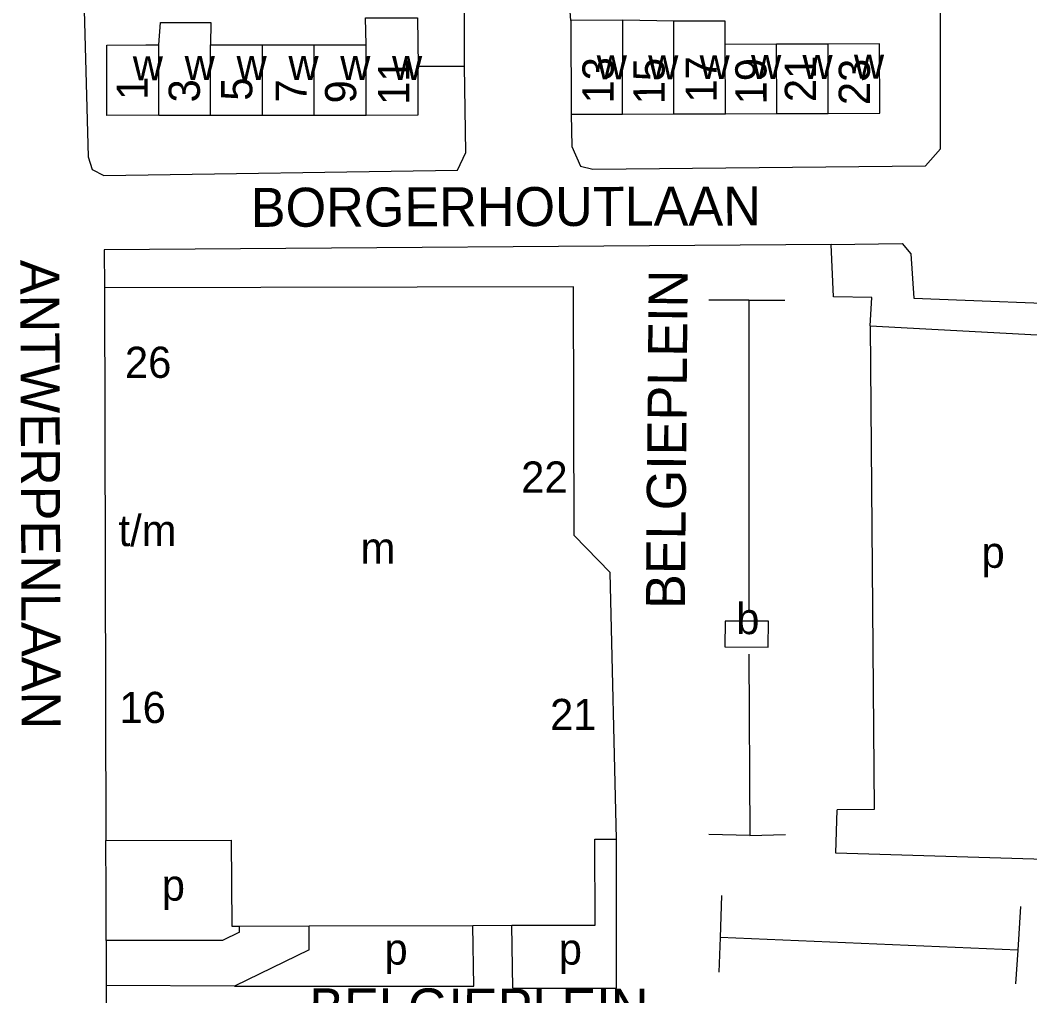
# Model space of a CAD drawing. Extents: x 159675 to 162108, y 386471 to 388472.
# Drawn here: x 161304.5 to 161434, y 387808.6 to 387933.7 of the extents above; entities that cross this region are included whole.
import ezdxf

# ---------------------------------------------------------------- set-up
doc = ezdxf.new("R2010")
doc.units = 0
for name, color, linetype in [('BLT_Basislijn', 7, 'Continuous'), ('BLT_Bebouwing', 7, 'Continuous'), ('BLT_Centroide', 7, 'Continuous'), ('BLT_Huisnummer', 7, 'Continuous'), ('BLT_Huisnummer_ tussenligend', 7, 'Continuous'), ('BLT_Huisnummer_reeks', 7, 'Continuous'), ('BLT_Onderverdeling_panden', 7, 'Continuous'), ('BLT_Straatnaam', 7, 'Continuous')]:
    doc.layers.add(name, color=color, linetype=linetype)

msp = doc.modelspace()

# ---------------------------------------------------------------- linework, layer by layer
at = {"layer": 'BLT_Basislijn'}
for p, q in [((161375.14, 387933.65), (161374.57, 387941.33)), ((161397.94, 387897.77), (161392.79, 387897.77)), ((161397.94, 387897.77), (161397.94, 387857.87)), ((161397.94, 387897.77), (161402.54, 387897.77)), ((161397.94, 387852.39), (161398.05, 387829.15)), ((161398.05, 387829.15), (161392.79, 387829.26)), ((161398.05, 387829.15), (161402.65, 387829.26)), ((161315.54, 387821.95), (161315.52, 387828.52)), ((161315.55, 387815.7), (161315.54, 387821.95)), ((161394.43, 387821.48), (161394.24, 387816.08)), ((161432.75, 387820.03), (161432.4, 387814.45)), ((161332.63, 387816.75), (161332.63, 387817.54)), ((161341.57, 387814.48), (161341.57, 387817.57)), ((161332.63, 387816.75), (161330.46, 387815.69)), ((161394.24, 387816.08), (161394.09, 387811.61)), ((161432.4, 387814.45), (161394.24, 387816.08)), ((161330.46, 387815.69), (161315.55, 387815.7)), ((161315.55, 387815.7), (161315.57, 387809.92)), ((161341.57, 387814.48), (161331.99, 387809.85)), ((161432.4, 387814.45), (161432.13, 387810.12)), ((161331.99, 387809.85), (161315.57, 387809.92))]:
    msp.add_line(p, q, dxfattribs=at)
for points in [[(161312.58, 387941.29), (161313.26, 387916.16), (161313.76, 387914.54), (161315.26, 387913.76), (161360.61, 387914.46), (161361.64, 387916.71), (161361.51, 387927.79)], [(161375.15, 387921.63), (161375.25, 387917.5), (161376.36, 387914.95), (161377.93, 387914.57), (161420.6, 387915), (161422.51, 387917.18), (161422.49, 387941.42)], [(161408.47, 387904.91), (161315.29, 387904.23), (161315.36, 387899.38)], [(161413.49, 387894.51), (161413.7, 387898.12), (161408.79, 387898.21), (161408.47, 387904.91), (161417.61, 387905.07), (161418.69, 387903.72), (161419.07, 387898.05), (161443.21, 387897.09)], [(161413.49, 387894.51), (161413.98, 387832.49), (161409.25, 387832.46)], [(161413.49, 387894.51), (161448.36, 387892.63), (161445.64, 387825.75), (161438.69, 387825.97)], [(161438.69, 387825.97), (161409.07, 387826.9), (161409.25, 387832.46)], [(161367.68, 387809.59), (161380.97, 387809.59), (161380.97, 387828.67)], [(161331.99, 387809.85), (161362.67, 387809.85), (161362.55, 387817.63)], [(161367.68, 387809.59), (161367.55, 387817.64)], [(161315.57, 387809.92), (161315.56, 387803.24)]]:
    msp.add_lwpolyline(points, dxfattribs=at)
at = {"layer": 'BLT_Bebouwing'}
for p, q in [((161361.51, 387927.79), (161361.5, 387939.92)), ((161375.14, 387933.65), (161375.15, 387921.63)), ((161388.34, 387933.56), (161381.79, 387933.67)), ((161328.94, 387930.51), (161335.59, 387930.52)), ((161335.59, 387930.52), (161342.23, 387930.52)), ((161342.23, 387930.52), (161348.88, 387930.53)), ((161401.5, 387930.6), (161394.91, 387930.58)), ((161408.1, 387930.61), (161401.5, 387930.6)), ((161355.53, 387927.78), (161361.51, 387927.79)), ((161322.3, 387921.49), (161328.95, 387921.49)), ((161328.95, 387921.49), (161335.6, 387921.5)), ((161335.6, 387921.5), (161342.24, 387921.51)), ((161342.24, 387921.51), (161348.89, 387921.52)), ((161375.15, 387921.63), (161381.74, 387921.65)), ((161381.74, 387921.65), (161388.34, 387921.67)), ((161388.34, 387921.67), (161394.93, 387921.69)), ((161394.93, 387921.69), (161401.53, 387921.71)), ((161401.53, 387921.71), (161408.12, 387921.73)), ((161380.97, 387828.67), (161380.17, 387862.88)), ((161332.63, 387817.54), (161341.57, 387817.57)), ((161341.57, 387817.57), (161362.55, 387817.63))]:
    msp.add_line(p, q, dxfattribs=at)
for points in [[(161348.88, 387930.53), (161348.8, 387933.98), (161355.48, 387933.98)], [(161322.29, 387930.5), (161322.54, 387933.37), (161328.98, 387933.38), (161328.94, 387930.51)], [(161381.79, 387933.67), (161375.14, 387933.65)], [(161394.91, 387930.58), (161394.9, 387933.57), (161388.34, 387933.56)], [(161322.3, 387921.49), (161315.66, 387921.48), (161315.65, 387930.49), (161320.65, 387930.5), (161322.29, 387930.5)], [(161408.12, 387921.73), (161414.71, 387921.75), (161414.69, 387930.64), (161408.1, 387930.61)], [(161348.89, 387921.52), (161355.54, 387921.53), (161355.53, 387927.78)], [(161380.17, 387862.88), (161375.54, 387867.6), (161375.46, 387899.5), (161315.36, 387899.38), (161315.52, 387828.52)], [(161394.9, 387856.64), (161394.87, 387853.32), (161400.4, 387853.29), (161400.44, 387856.64), (161394.9, 387856.64)], [(161315.52, 387828.52), (161331.59, 387828.55), (161331.67, 387817.54), (161332.63, 387817.54)], [(161367.55, 387817.64), (161378.25, 387817.67), (161378.19, 387828.66)], [(161378.19, 387828.66), (161380.97, 387828.67)], [(161362.55, 387817.63), (161367.55, 387817.64)]]:
    msp.add_lwpolyline(points, dxfattribs=at)
at = {"layer": 'BLT_Onderverdeling_panden'}
for p, q in [((161355.48, 387933.98), (161355.53, 387927.78)), ((161381.74, 387921.65), (161381.79, 387933.67)), ((161388.34, 387921.67), (161388.34, 387933.56)), ((161322.3, 387921.49), (161322.29, 387930.5)), ((161328.95, 387921.49), (161328.94, 387930.51)), ((161335.6, 387921.5), (161335.59, 387930.52)), ((161342.24, 387921.51), (161342.23, 387930.52)), ((161348.89, 387921.52), (161348.88, 387930.53)), ((161394.93, 387921.69), (161394.91, 387930.58)), ((161401.53, 387921.71), (161401.5, 387930.6)), ((161408.12, 387921.73), (161408.1, 387930.61))]:
    msp.add_line(p, q, dxfattribs=at)

# ---------------------------------------------------------------- texts
at = {"layer": 'BLT_Centroide'}
for s, p in [('w', (161318.97, 387925.98)), ('w', (161325.62, 387926)), ('w', (161332.27, 387926)), ('w', (161338.92, 387926.02)), ('w', (161345.56, 387926.02)), ('w', (161352.2, 387926.03)), ('w', (161378.44, 387926.09)), ('w', (161385.03, 387926.09)), ('w', (161391.62, 387926.12)), ('w', (161398.22, 387926.14)), ('w', (161404.81, 387926.16)), ('w', (161411.41, 387926.19)), ('m', (161348.17, 387864.02)), ('p', (161427.76, 387863.47)), ('b', (161396.32, 387854.97)), ('p', (161322.68, 387820.8)), ('p', (161351.23, 387812.6)), ('p', (161373.57, 387812.6))]:
    msp.add_text(s, height=4, dxfattribs=at).set_placement(p)
at = {"layer": 'BLT_Huisnummer'}
for s, rotation, p in [('13', 89.8323, (161380.59, 387922.99)), ('17', 89.8323, (161393.82, 387923.11)), ('11', 89.9301, (161354.41, 387922.81)), ('23', 89.8323, (161413.45, 387922.78)), ('1', 89.9301, (161320.88, 387923.46)), ('5', 89.9301, (161334.29, 387923.35))]:
    msp.add_text(s, height=4, rotation=rotation, dxfattribs=at).set_placement(p)
at = {"layer": 'BLT_Huisnummer_ tussenligend'}
for s, rotation, p in [('15', 90.1677, (161387.15, 387922.9)), ('21', 90.1677, (161406.55, 387923.19)), ('19', 90.1677, (161400.21, 387922.89)), ('3', 90.0699, (161327.57, 387923.14)), ('7', 90.0699, (161341.27, 387923.13)), ('9', 90.0699, (161347.61, 387923.01))]:
    msp.add_text(s, height=4, rotation=rotation, dxfattribs=at).set_placement(p)
at = {"layer": 'BLT_Huisnummer_reeks'}
for s, rotation, p in [('26', 0.1691, (161317.97, 387887.81)), ('22', 0.1424, (161368.76, 387873.1)), ('t/m', 0.1691, (161317.15, 387866.25)), ('16', 0.1691, (161317.26, 387843.56)), ('21', 0.1424, (161372.46, 387842.66))]:
    msp.add_text(s, height=4, rotation=rotation, dxfattribs=at).set_placement(p)
at = {"layer": 'BLT_Straatnaam'}
for s, height, rotation, p in [('BORGERHOUTLAAN', 5, 0.1638, (161334.1, 387907.18)), ('ANTWERPENLAAN', 5, 270.1924, (161304.54, 387902.96)), ('BELGIEPLEIN', 4.9999, 89.4997, (161389.73, 387858.18)), ('BELGIEPLEIN', 5, 359.9148, (161341.58, 387804.56))]:
    msp.add_text(s, height=height, rotation=rotation, dxfattribs=at).set_placement(p)

doc.saveas('drawing.dxf')
